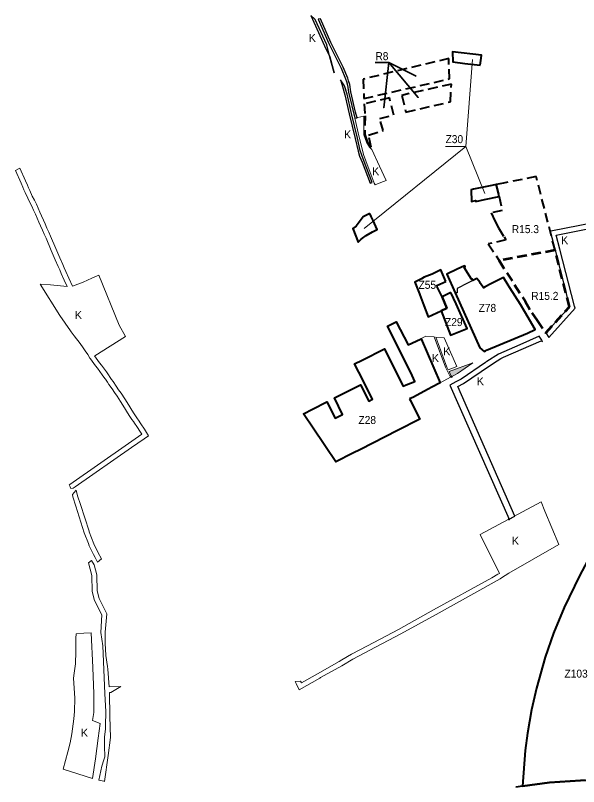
# Model space of a CAD drawing. Extents: x -650276 to -642489, y -1074311 to -1066658.
# Drawn here: x -649558 to -647871, y -1068970 to -1066658 of the extents above; entities that cross this region are included whole.
import ezdxf

# ---------------------------------------------------------------- set-up
doc = ezdxf.new("R2010")
doc.units = 0
doc.header["$LTSCALE"] = 9.6
doc.header["$PDMODE"] = 32
doc.header["$PDSIZE"] = 4.8
doc.linetypes.add('MEDIUM_DASHED', pattern=[4.5, 3, -1.5])
for name, color, linetype, lineweight in [('42', 7, 'Continuous', 25), ('44', 7, 'Continuous', 40), ('45', 7, 'Continuous', 40), ('46', 7, 'Continuous', 13), ('47', 7, 'Continuous', 13), ('48', 7, 'Continuous', 13), ('61', 7, 'MEDIUM_DASHED', 40), ('62', 7, 'Continuous', 35)]:
    doc.layers.add(name, color=color, linetype=linetype, lineweight=lineweight)

msp = doc.modelspace()

# ---------------------------------------------------------------- hatches: boundary and pattern name
at = {"layer": '47'}
msp.add_hatch(color=256, dxfattribs=at).paths.add_polyline_path([(-648258.96, -1067725.37), (-648251.711, -1067741.124), (-648233.264, -1067731.288), (-648187.139, -1067699.179)])

# ---------------------------------------------------------------- linework, layer by layer
at = {"layer": '42'}
msp.add_lwpolyline([(-648153.98, -1067665.43), (-648149.933, -1067663.646), (-648146.21, -1067661.3), (-648023.96, -1067610.13), (-648000.63, -1067599.14), (-648031.77, -1067546.6), (-648045.04, -1067525.15), (-648076.32, -1067474.6), (-648081.31, -1067466.54), (-648095.28, -1067444.06), (-648133.56, -1067463.2), (-648150.46, -1067471.66), (-648155.85, -1067474.35), (-648164.24, -1067462.15), (-648166.97, -1067458.18), (-648170.38, -1067453.23), (-648175.94, -1067446.89), (-648187.44, -1067452.8), (-648203.39, -1067460.99), (-648234.68, -1067477.06), (-648234.87, -1067489.9), (-648240.51, -1067489.9), (-648166.173, -1067654.853)], close=True, dxfattribs=at)
at = {"layer": '44'}
for points in [[(-647801.168, -1068218.237), (-647843.6, -1068292.629), (-647868.214, -1068337.803), (-647914.339, -1068432.512), (-647946.187, -1068510.254), (-647971.074, -1068581.98), (-647997.27, -1068674.747), (-648011.775, -1068739.718), (-648023.914, -1068809.332), (-648030.73, -1068861.213), (-648038.596, -1068968.281), (-647958.168, -1068957.73)], [(-647749.978, -1068953.416), (-647850.043, -1068951.099), (-647864.531, -1068951.823), (-647895.901, -1068953.392), (-647958.168, -1068957.73), (-648038.596, -1068968.281), (-648038.596, -1068968.281), (-648038.746, -1068968.301), (-648058.764, -1068970.927)], [(-647958.168, -1068957.73), (-647895.901, -1068953.392), (-647864.531, -1068951.823)]]:
    msp.add_lwpolyline(points, dxfattribs=at)
at = {"layer": '45'}
for points in [[(-648165.33, -1066807.74), (-648162.8, -1066786.8), (-648161.58, -1066777.41), (-648248.77, -1066767.43), (-648247.78, -1066797.53), (-648211.58, -1066802.18)], [(-648165.33, -1066807.74), (-648162.8, -1066786.8), (-648161.58, -1066777.41), (-648248.77, -1066767.43), (-648247.78, -1066797.53), (-648211.58, -1066802.18)], [(-648185.185, -1067178.687), (-648193.02, -1067180.66), (-648191.44, -1067215.62), (-648179.42, -1067213.37), (-648179, -1067215.71), (-648152.5, -1067210.23), (-648109.1, -1067201.21), (-648117.51, -1067165.42), (-648131.01, -1067167.84)], [(-648185.185, -1067178.687), (-648193.02, -1067180.66), (-648191.44, -1067215.62), (-648179.42, -1067213.37), (-648179, -1067215.71), (-648152.5, -1067210.23), (-648109.1, -1067201.21), (-648117.51, -1067165.42), (-648131.01, -1067167.84)], [(-648496.55, -1067251.53), (-648516.47, -1067261.54), (-648536.84, -1067290.29), (-648547.17, -1067296.68), (-648531.51, -1067337.57), (-648523.55, -1067330.33), (-648518.55, -1067326.3), (-648507.25, -1067318.35), (-648488.66, -1067307.11), (-648474.69, -1067299.66), (-648486.79, -1067273.26), (-648492.62, -1067260.53)], [(-648496.55, -1067251.53), (-648516.47, -1067261.54), (-648536.84, -1067290.29), (-648547.17, -1067296.68), (-648531.51, -1067337.57), (-648523.55, -1067330.33), (-648518.55, -1067326.3), (-648507.25, -1067318.35), (-648488.66, -1067307.11), (-648474.69, -1067299.66), (-648486.79, -1067273.26), (-648492.62, -1067260.53)], [(-648153.98, -1067665.43), (-648149.933, -1067663.646), (-648146.21, -1067661.3), (-648023.96, -1067610.13), (-648000.63, -1067599.14), (-648031.77, -1067546.6), (-648045.04, -1067525.15), (-648076.32, -1067474.6), (-648081.31, -1067466.54), (-648095.28, -1067444.06), (-648133.56, -1067463.2), (-648150.46, -1067471.66), (-648155.85, -1067474.35), (-648164.24, -1067462.15), (-648166.97, -1067458.18), (-648170.38, -1067453.23), (-648175.94, -1067446.89), (-648187.44, -1067452.8), (-648190.23, -1067447.83), (-648191.46, -1067448.59), (-648213.34, -1067413.46), (-648210.48, -1067411.68), (-648212.32, -1067408.39), (-648234.808, -1067419.29), (-648265.197, -1067434.03), (-648240.51, -1067489.9), (-648166.173, -1067654.853)], [(-648153.98, -1067665.43), (-648149.933, -1067663.646), (-648146.21, -1067661.3), (-648023.96, -1067610.13), (-648000.63, -1067599.14), (-648031.77, -1067546.6), (-648045.04, -1067525.15), (-648076.32, -1067474.6), (-648081.31, -1067466.54), (-648095.28, -1067444.06), (-648133.56, -1067463.2), (-648150.46, -1067471.66), (-648155.85, -1067474.35), (-648164.24, -1067462.15), (-648166.97, -1067458.18), (-648170.38, -1067453.23), (-648175.94, -1067446.89), (-648187.44, -1067452.8), (-648190.23, -1067447.83), (-648191.46, -1067448.59), (-648213.34, -1067413.46), (-648210.48, -1067411.68), (-648212.32, -1067408.39), (-648234.808, -1067419.29), (-648265.197, -1067434.03), (-648240.51, -1067489.9), (-648166.173, -1067654.853)], [(-648253.1, -1067489.23), (-648279.86, -1067502.11), (-648265.757, -1067535.555), (-648282.863, -1067543.596), (-648254.04, -1067616.96), (-648204.88, -1067596.54), (-648237.81, -1067522.42)]]:
    msp.add_lwpolyline(points, close=True, dxfattribs=at)
for points in [[(-648268.67, -1067455.43), (-648283.21, -1067420.88), (-648295.66, -1067426.76), (-648309.57, -1067433.34), (-648333.48, -1067443.28), (-648341.15, -1067448.14)], [(-648341.15, -1067448.14), (-648361, -1067457.36), (-648347.51, -1067492.87)], [(-648279.86, -1067502.11), (-648294.04, -1067471.35), (-648295.409, -1067468.129), (-648268.67, -1067455.43)], [(-648347.51, -1067492.87), (-648346.27, -1067496.14), (-648334.09, -1067528.2), (-648321.36, -1067561.69), (-648282.863, -1067543.596)], [(-648282.863, -1067543.596), (-648265.757, -1067535.555), (-648279.86, -1067502.11)], [(-648433.183, -1067696.369), (-648396.605, -1067769.277), (-648387.04, -1067765.67), (-648361.08, -1067755.88), (-648369.832, -1067737.624), (-648397.98, -1067678.79), (-648443.83, -1067589.92), (-648417.12, -1067576.17), (-648381.535, -1067645.274), (-648369.949, -1067640.851), (-648342.023, -1067628.096), (-648285.254, -1067759.008), (-648310.511, -1067772.476), (-648321.623, -1067778.399), (-648367.811, -1067802.994), (-648370.113, -1067804.22), (-648377.422, -1067807.337)], [(-648377.422, -1067807.337), (-648374.84, -1067812.43), (-648371.27, -1067819.47), (-648346.57, -1067868.56), (-648413.41, -1067902.53), (-648524.72, -1067958.93), (-648546.76, -1067970.44), (-648597.93, -1067996.72), (-648629.22, -1067950.214), (-648635.249, -1067941.252), (-648664.41, -1067897.91), (-648695.27, -1067852.04), (-648668.085, -1067838.186), (-648624.76, -1067816.11), (-648600.14, -1067865.29), (-648577.78, -1067854.07), (-648602.3, -1067804.83), (-648580.14, -1067793.61), (-648524.44, -1067765.11), (-648499.7, -1067814.37), (-648488.49, -1067808.76), (-648513.23, -1067759.38), (-648516.73, -1067752.57), (-648541.86, -1067702.86), (-648519.63, -1067691.58), (-648452.72, -1067657.62), (-648433.183, -1067696.369)]]:
    msp.add_lwpolyline(points, dxfattribs=at)
at = {"layer": '46'}
msp.add_lwpolyline([(-648269.459, -1067050.713), (-648208.812, -1067050.713), (-648188.893, -1066790.602), (-648208.812, -1067050.713), (-648151.62, -1067191.569), (-648208.812, -1067050.713), (-648513.485, -1067297.251)], dxfattribs=at)
msp.add_lwpolyline([(-648269.459, -1067050.713), (-648208.812, -1067050.713), (-648188.893, -1066790.602), (-648208.812, -1067050.713), (-648151.62, -1067191.569), (-648208.812, -1067050.713), (-648513.485, -1067297.251)], dxfattribs=at)
at = {"layer": '47'}
msp.add_line((-648108.158, -1068330.583), (-648112.198, -1068333.037), dxfattribs=at)
at = {"layer": '47', "lineweight": 25}
for points in [[(-648602.97, -1066830.11), (-648616.86, -1066779.79), (-648625.44, -1066746.45), (-648659.95, -1066670.89), (-648662.46, -1066668.53), (-648673.407, -1066658.275), (-648631.791, -1066749.394)], [(-648534.701, -1066965.077), (-648538.812, -1066947.891), (-648553.323, -1066887.238), (-648556.637, -1066865.397), (-648559.94, -1066854.66), (-648562.542, -1066846.219), (-648576.145, -1066813.802), (-648612.763, -1066739.165), (-648643.925, -1066668.483), (-648651.042, -1066669.551), (-648651.1, -1066669.56)], [(-648651.1, -1066669.56), (-648619.11, -1066742.12), (-648582.52, -1066816.7)], [(-648631.791, -1066749.394), (-648616.104, -1066782.727), (-648602.97, -1066830.11)], [(-648582.52, -1066816.7), (-648569.13, -1066848.61), (-648566.63, -1066856.72), (-648563.48, -1066866.96), (-648560.2, -1066888.58), (-648541.521, -1066966.657), (-648534.701, -1066965.077)], [(-648571.96, -1066869.37), (-648577.99, -1066860.17), (-648583.94, -1066851.11)], [(-648583.94, -1066851.11), (-648578.702, -1066871.259), (-648571.167, -1066896.326), (-648557.816, -1066953.444)], [(-648489.1, -1067158.84), (-648512.95, -1067095.97), (-648520.4, -1067077.42), (-648524.93, -1067063.35), (-648533.66, -1067026), (-648551, -1066951.85), (-648564.4, -1066894.52), (-648571.96, -1066869.37)], [(-648557.816, -1066953.444), (-648540.476, -1067027.594), (-648531.681, -1067065.222)], [(-648531.681, -1067065.222), (-648526.988, -1067079.8), (-648519.471, -1067098.516), (-648495.644, -1067161.326), (-648489.1, -1067158.84)], [(-647882.66, -1067529.231), (-647926.759, -1067358.379), (-647937.355, -1067316.774), (-647828.376, -1067295.406), (-647828.104, -1067295.352), (-647831.28, -1067280.69), (-647948.488, -1067303.671)], [(-647948.488, -1067303.671), (-647955.805, -1067305.106), (-647941.289, -1067362.104)], [(-647941.289, -1067362.104), (-647897.637, -1067531.223), (-647969.29, -1067609.79), (-647959.832, -1067623.65)], [(-647959.832, -1067623.65), (-647881.085, -1067535.333), (-647882.66, -1067529.231)], [(-647978.705, -1067635.817), (-647982.95, -1067628.73), (-647988.334, -1067619.747), (-648046.773, -1067645.314)], [(-648046.773, -1067645.314), (-648110.36, -1067673.133), (-648146.127, -1067695.8), (-648146.146, -1067695.813), (-648149.529, -1067698.132), (-648222.53, -1067748.178)], [(-648095.475, -1067682.994), (-647983.06, -1067633.813), (-647978.705, -1067635.817)], [(-648232.676, -1067770.513), (-648215.115, -1067761.28), (-648137.869, -1067708.325), (-648114.323, -1067693.403), (-648103.298, -1067686.416), (-648095.475, -1067682.994)], [(-648238.748, -1067756.759), (-648256.499, -1067766.091), (-648079.002, -1068168.139)], [(-648222.53, -1067748.178), (-648222.872, -1067748.412), (-648238.748, -1067756.759)], [(-648079.002, -1068168.139), (-648061.329, -1068158.649), (-648232.676, -1067770.513)]]:
    msp.add_lwpolyline(points, dxfattribs=at)
at = {"layer": '47'}
for points in [[(-648490.23, -1067060.06), (-648496.87, -1067053.5), (-648506.78, -1067037.81), (-648514.38, -1067016.2), (-648513.842, -1066960.243), (-648541.52, -1066966.657), (-648528.01, -1067023.13)], [(-648528.01, -1067023.13), (-648518.72, -1067061.99), (-648514.86, -1067074.83), (-648507.88, -1067093.9), (-648483.31, -1067160.63), (-648480.57, -1067166.13)], [(-648480.57, -1067166.13), (-648462.97, -1067159.24), (-648447.66, -1067153.25), (-648467.56, -1067110.02), (-648490.23, -1067060.06)], [(-649545.203, -1067115.647), (-649549.7, -1067118.05), (-649558.469, -1067122.73), (-649541.537, -1067160.722), (-649536.075, -1067172.622), (-649532.831, -1067180.855), (-649529.013, -1067189.389), (-649521.663, -1067206.124), (-649514.869, -1067218.957), (-649509.44, -1067230.141), (-649504.224, -1067242.225), (-649498.572, -1067254.427), (-649493.526, -1067265.611), (-649487.812, -1067278.312), (-649482.963, -1067288.934), (-649477.677, -1067301.655), (-649472.327, -1067313.644), (-649466.703, -1067326.24), (-649451.059, -1067363.074), (-649439.265, -1067390.397), (-649430.531, -1067410.689), (-649425.804, -1067421.21), (-649421.071, -1067431.944), (-649411.913, -1067451.746), (-649403.34, -1067470.579)], [(-649387.17, -1067469.894), (-649398.28, -1067445.49), (-649407.4, -1067425.77), (-649412.1, -1067415.11), (-649416.8, -1067404.65), (-649425.49, -1067384.46), (-649437.27, -1067357.17), (-649452.95, -1067320.25), (-649458.63, -1067307.53), (-649463.9, -1067295.72), (-649469.21, -1067282.94), (-649474.15, -1067272.12), (-649479.85, -1067259.45), (-649484.93, -1067248.19), (-649490.53, -1067236.1), (-649495.8, -1067223.89), (-649501.49, -1067212.17), (-649508.15, -1067199.59), (-649515.3, -1067183.31), (-649519, -1067175.04), (-649522.27, -1067166.74), (-649527.87, -1067154.54), (-649545.203, -1067115.647)], [(-649321.3, -1067679), (-649320.47, -1067678.44), (-649228.52, -1067620.294), (-649247.518, -1067586.255), (-649308.75, -1067437.11), (-649329.068, -1067446.175), (-649355.44, -1067457.94), (-649387.17, -1067469.894)], [(-649403.34, -1067470.579), (-649453.39, -1067466.13), (-649484.28, -1067463.88), (-649425.69, -1067557.7), (-649393.23, -1067603.28), (-649391.04, -1067606.27), (-649382.53, -1067618.33), (-649364.69, -1067641.98), (-649355.46, -1067654.85), (-649349.12, -1067663.84), (-649341.81, -1067674.33), (-649335.26, -1067685.21), (-649333.74, -1067687.4)], [(-649333.74, -1067687.4), (-649328.34, -1067694.79), (-649317.99, -1067708.85), (-649312.91, -1067715.45), (-649298.02, -1067735.58), (-649290.15, -1067746.92), (-649288.63, -1067748.97), (-649282.85, -1067757.79), (-649278.14, -1067764.31), (-649268.46, -1067777.97), (-649261.48, -1067788.47), (-649253.98, -1067799.2), (-649243.37, -1067815.17), (-649241.28, -1067818.7), (-649228.27, -1067839.26), (-649222.11, -1067849.12), (-649215.32, -1067859.99), (-649209.39, -1067869.34), (-649204.87, -1067875.85), (-649202.02, -1067880.07), (-649194.77, -1067890.67), (-649184, -1067906.88), (-649179.96, -1067913.35), (-649219.088, -1067940.964), (-649395.729, -1068064.23), (-649397.466, -1068065.442), (-649394.83, -1068071.05), (-649392.88, -1068075.9), (-649385.41, -1068075.32), (-649379.295, -1068071.053), (-649210.54, -1067953.29), (-649172.99, -1067927.41), (-649159.179, -1067918.309), (-649171.389, -1067898.756), (-649182.332, -1067882.285), (-649189.614, -1067871.638), (-649192.493, -1067867.375), (-649196.89, -1067861.042), (-649202.625, -1067852), (-649209.388, -1067841.173), (-649215.571, -1067831.276), (-649228.486, -1067810.867), (-649230.661, -1067807.193), (-649241.584, -1067790.752), (-649249.085, -1067780.02), (-649256.092, -1067769.48), (-649265.941, -1067755.582), (-649270.491, -1067749.283), (-649276.322, -1067740.385), (-649277.961, -1067738.175), (-649285.826, -1067726.842), (-649300.936, -1067706.414), (-649306.005, -1067699.828), (-649316.244, -1067685.919), (-649321.3, -1067679)], [(-649376.467, -1068081.552), (-649377.77, -1068082.44), (-649387.46, -1068094.51), (-649386.74, -1068101.31), (-649377.81, -1068129), (-649352.11, -1068208.65)], [(-649352.11, -1068208.65), (-649339.94, -1068241.13), (-649337.52, -1068247.59), (-649324.66, -1068274.3), (-649319.551, -1068283.382), (-649312.087, -1068296.653), (-649300.305, -1068287.002), (-649311.352, -1068267.362), (-649323.711, -1068241.693), (-649337.178, -1068205.751), (-649337.942, -1068203.713), (-649363.534, -1068124.395), (-649371.987, -1068098.185), (-649376.467, -1068081.552)], [(-648101.42, -1068344.28), (-648079.33, -1068330.03), (-647929.45, -1068244.16), (-647971.35, -1068144.48), (-647982.969, -1068116.575), (-648165.28, -1068214.465), (-648108.158, -1068330.583)], [(-649330.038, -1068291.976), (-649339.046, -1068299.359), (-649329.644, -1068336.779), (-649328.386, -1068384.468), (-649321.727, -1068411.472), (-649299.894, -1068454.728), (-649302.681, -1068507.363)], [(-649289.24, -1068506.8), (-649284.59, -1068451.76), (-649307.57, -1068406.23), (-649313.42, -1068382.51), (-649314.27, -1068336.41), (-649314.693, -1068334.727), (-649322.18, -1068304.93), (-649330.038, -1068291.976)], [(-648112.198, -1068333.037), (-648112.92, -1068333.424), (-648131.034, -1068344.388), (-648305.242, -1068440.3), (-648410.111, -1068498.408), (-648503.768, -1068547.914), (-648551.041, -1068573.16)], [(-648547.25, -1068588.14), (-648496.73, -1068561.16), (-648402.97, -1068511.6), (-648297.99, -1068453.43), (-648123.53, -1068357.38), (-648105.49, -1068346.46), (-648101.42, -1068344.28)], [(-649327.679, -1068945.222), (-649318.13, -1068886.42), (-649314.07, -1068855.33), (-649310.01, -1068824.2), (-649304.66, -1068780.33), (-649327.8, -1068771.82), (-649323.68, -1068748.06), (-649323.1, -1068699.28), (-649323.02, -1068692.1), (-649326.53, -1068612.89), (-649331.151, -1068508.557), (-649353.17, -1068509.48), (-649376.77, -1068511.96), (-649377.52, -1068525.1), (-649377.56, -1068564.89), (-649378.08, -1068601.24), (-649382.46, -1068629.34), (-649384.31, -1068644.92), (-649379.97, -1068704.98), (-649381.06, -1068744.69), (-649383.78, -1068766.6)], [(-649302.681, -1068507.363), (-649296.55, -1068548.09), (-649290.93, -1068690.93), (-649287.98, -1068745.74), (-649288.19, -1068786.39), (-649288.24, -1068796.6), (-649291.64, -1068821.88), (-649291.87, -1068848.02), (-649290.28, -1068880.82), (-649293.33, -1068889.65), (-649299.91, -1068908.66), (-649308.65, -1068950), (-649293.04, -1068953.81), (-649291.32, -1068954.23), (-649281.01, -1068876.69), (-649273.66, -1068822.58), (-649275.96, -1068759.73), (-649276.43, -1068688.29), (-649276.474, -1068687.673), (-649272.755, -1068687.618)], [(-649277.655, -1068670.983), (-649281.4, -1068618.05), (-649282.97, -1068610.04), (-649287.71, -1068577.14), (-649289.74, -1068540.2), (-649289.24, -1068506.8)], [(-648551.041, -1068573.16), (-648580.062, -1068590.087), (-648588.022, -1068594.571), (-648653.034, -1068631.191), (-648701.568, -1068658.36), (-648703.816, -1068653.711), (-648720.238, -1068654.205)], [(-648720.238, -1068654.205), (-648717.32, -1068660.24), (-648708.14, -1068679.23), (-648645.69, -1068644.27), (-648643.654, -1068643.123), (-648580.66, -1068607.64), (-648547.25, -1068588.14)], [(-649272.755, -1068687.618), (-649272.69, -1068687.58), (-649242.507, -1068669.925), (-649277.655, -1068670.983)], [(-649383.78, -1068766.6), (-649389.34, -1068811.43), (-649394.48, -1068838.89), (-649401.31, -1068865.78), (-649415.09, -1068917.1), (-649327.679, -1068945.222)]]:
    msp.add_lwpolyline(points, dxfattribs=at)
for points in [[(-648303.68, -1067621.697), (-648328.54, -1067619.51), (-648342.697, -1067626.806), (-648296.891, -1067732.172), (-648285.254, -1067759.008), (-648255.016, -1067742.886), (-648265.614, -1067720.378), (-648269.27, -1067712.6)], [(-648298.632, -1067622.141), (-648273.229, -1067624.376), (-648235.78, -1067710.79), (-648261.25, -1067720.39), (-648265.08, -1067712.06)], [(-648258.96, -1067725.37), (-648251.711, -1067741.124), (-648233.264, -1067731.288), (-648187.139, -1067699.179)]]:
    msp.add_lwpolyline(points, close=True, dxfattribs=at)
for p in [(-648251.711, -1067741.124), (-648079.002, -1068168.139)]:
    msp.add_point(p, dxfattribs=at)
at = {"layer": '61'}
for points in [[(-648259.725, -1066787.254), (-648516.098, -1066849.061), (-648514.246, -1066907.231), (-648257.498, -1066848.545)], [(-648251.815, -1066863.877), (-648400.574, -1066897.877), (-648387.967, -1066948.136), (-648254.98, -1066916.96)], [(-648437.487, -1066905.774), (-648513.271, -1066923.097), (-648510.55, -1066959.48), (-648511.02, -1067015.58), (-648504.44, -1067035.85), (-648492.67, -1067053.5), (-648500.15, -1067017.22), (-648456.62, -1067003.59), (-648466.26, -1066967), (-648424.66, -1066956.87)]]:
    msp.add_lwpolyline(points, close=True, dxfattribs=at)
for points in [[(-647941.289, -1067362.104), (-647997.58, -1067141.08), (-648095.81, -1067160.82), (-648117.51, -1067165.42), (-648109.1, -1067201.21), (-648099.39, -1067242.54)], [(-648099.39, -1067242.54), (-648132.22, -1067250.27), (-648121.94, -1067274.29), (-648110.97, -1067294.96), (-648094.1, -1067322.05), (-648088.84, -1067331.19), (-648141.82, -1067342.88), (-648108.77, -1067393.23)]]:
    msp.add_lwpolyline(points, dxfattribs=at)
at = {"layer": '61', "lineweight": 53}
for points in [[(-647941.289, -1067362.104), (-648108.77, -1067393.23), (-648031.228, -1067515.162), (-648010.57, -1067549.31)], [(-648010.57, -1067549.31), (-647994.8, -1067572.37), (-647969.29, -1067609.79), (-647898.091, -1067531.72), (-647941.289, -1067362.104)]]:
    msp.add_lwpolyline(points, dxfattribs=at)
at = {"layer": '62'}
msp.add_lwpolyline([(-648480.094, -1066799.151), (-648438.938, -1066799.151), (-648454.468, -1066935.138), (-648438.938, -1066799.151), (-648351.131, -1066904.144), (-648438.938, -1066799.151), (-648357.401, -1066840.335)], dxfattribs=at)
at = {"layer": '62', "lineweight": 13}
msp.add_lwpolyline([(-648480.094, -1066799.151), (-648438.938, -1066799.151), (-648454.468, -1066935.138), (-648438.938, -1066799.151), (-648351.131, -1066904.144), (-648438.938, -1066799.151), (-648357.401, -1066840.335)], dxfattribs=at)

# ---------------------------------------------------------------- texts
at = {"layer": '44', "width": 0.95}
msp.add_text('Z103', height=24, dxfattribs=at).set_placement((-647912.849, -1068643.055))
at = {"layer": '46', "width": 0.95}
for s, p in [('Z30', (-648269.261, -1067041.062)), ('Z30', (-648269.261, -1067041.062)), ('Z55', (-648350.312, -1067477.755)), ('Z78', (-648170.304, -1067546.968)), ('Z29', (-648270.915, -1067589.341)), ('Z28', (-648530.318, -1067882.806))]:
    msp.add_text(s, height=24, dxfattribs=at).set_placement(p)
at = {"layer": '48'}
for p in [(-648679.318, -1066737.684), (-648573.703, -1067027.067), (-648489.516, -1067137.308), (-648489.516, -1067137.308), (-647923.173, -1067344.01), (-649380.314, -1067568.167), (-649380.314, -1067568.167), (-648276.169, -1067677.278), (-648310.251, -1067697.408), (-648175.732, -1067766.601), (-648070.59, -1068244.82), (-648070.59, -1068244.82), (-649362.16, -1068820.233), (-649362.16, -1068820.233)]:
    msp.add_text('K', height=24, dxfattribs=at).set_placement(p)
at = {"layer": '62', "width": 0.95}
for s, p in [('R8', (-648479.548, -1066792.4)), ('R8', (-648479.548, -1066792.4)), ('R15.3', (-648070.747, -1067310.744)), ('R15.2', (-648012.511, -1067510.868))]:
    msp.add_text(s, height=24, dxfattribs=at).set_placement(p)

doc.saveas('drawing.dxf')
